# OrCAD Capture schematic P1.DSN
size A
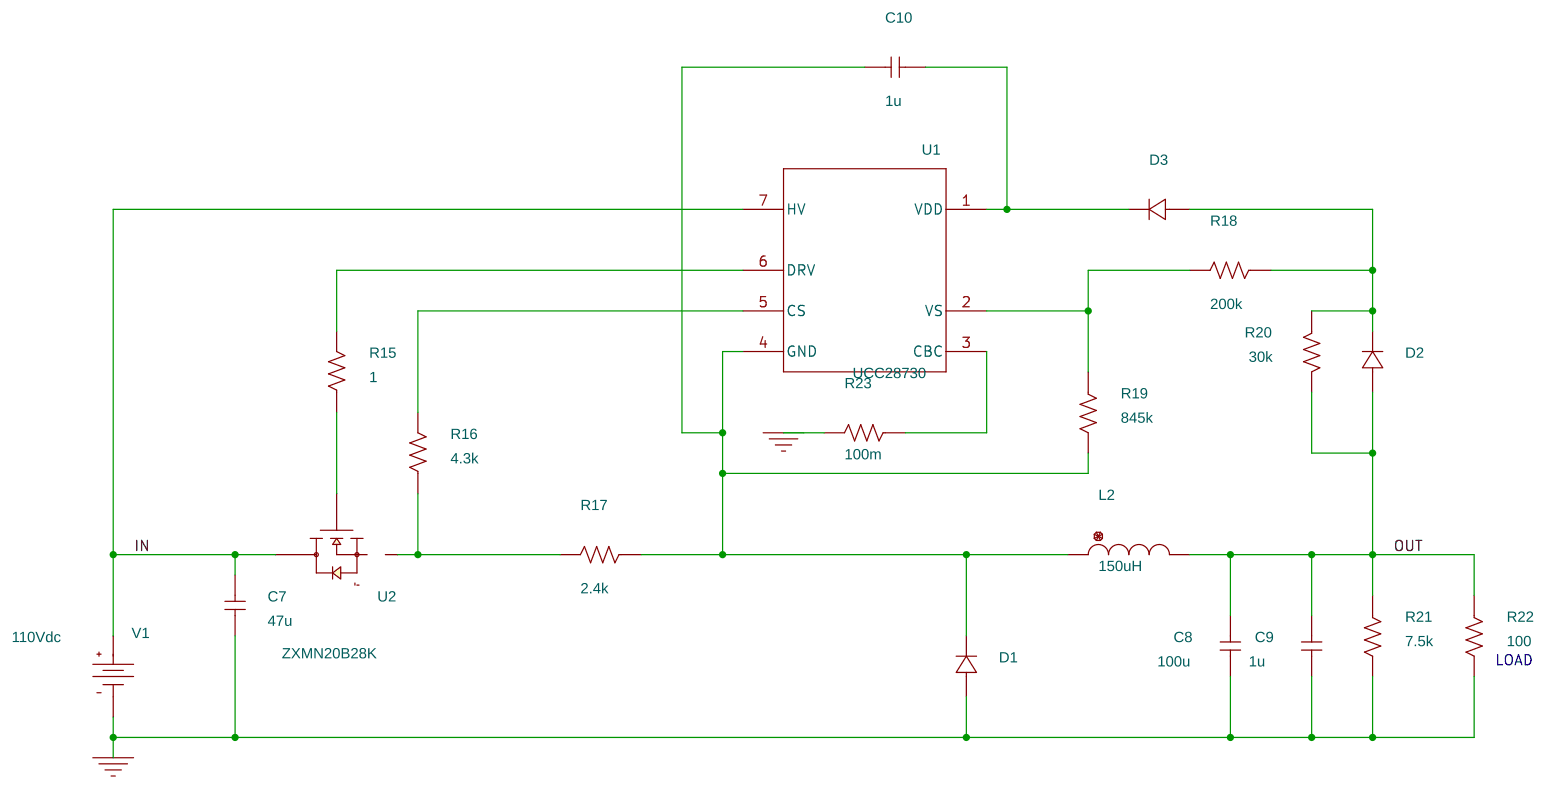
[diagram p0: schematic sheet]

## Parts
C7  47u  [cap196]
C8  100u  [cap196]
C9  1u  [cap196]
C10  1u  [cap196]
D1  Dbreak
D2  Dbreak
D3  Dbreak
L2  150uH  [DISC350x175LS200x100034]
R15  1  [AXRC05]
R16  4.3k  [AXRC05]
R17  2.4k  [AXRC05]
R18  200k  [AXRC05]
R19  845k  [AXRC05]
R20  30k  [AXRC05]
R21  7.5k  [AXRC05]
R22  100  [AXRC05]
R23  100m  [AXRC05]
U1  UCC28730
U2  ZXMN20B28K
V1  VDC

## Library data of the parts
C7-C10 = C
D1-D3 = Dbreak
L2 = L
R15-R23 = R
U1 = UCC28730_NETLIST: Testbenches: []; Version: 1; productURL: http://www.ti.com/document-viewer/UCC24650/datasheet/
U2 = ZXMN20B28K
V1 = VDC: DC: 110Vdc

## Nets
0: C7.1 C8.1 C9.1 D1.0(1) R21.2 R22.2 R23.2 V1.1(-)
IN: C7.2 U1.7(HV) U2.3(drain) V1.0(+)
OUT: C8.2 C9.2 D2.0(1) L2.2 R20.2 R21.1 R22.1
N00701: R15.2 U1.6(DRV)
N00719: R16.1 R17.2 U2.1(source)
N00801: R16.2 U1.5(CS)
N00887: C10.2 D1.1(2) L2.1 R17.1 R19.2 U1.4(GND)
N01106: D2.1(2) D3.0(1) R18.1 R20.1
N01228: R18.2 R19.1 U1.2(VS)
N01301: C10.1 D3.1(2) U1.1(VDD)
N02199: R15.1 U2.2(gate)
N02399: R23.1 U1.3(CBC)

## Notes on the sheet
- LOAD
